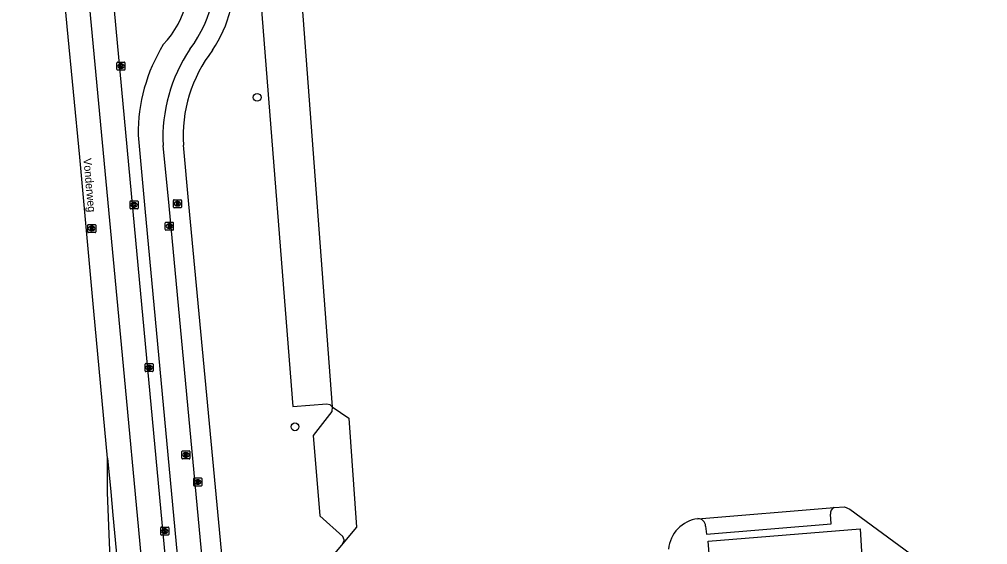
# Model space of a CAD drawing. Extents: x 160676 to 161153, y 383244 to 383713.
# Drawn here: x 160677.6 to 160798.6, y 383378.1 to 383443.8 of the extents above; entities that cross this region are included whole.
import ezdxf

# ---------------------------------------------------------------- set-up
doc = ezdxf.new("R2010")
doc.units = 0
for name, color, linetype in [('IMGEO_Boom', 7, 'Continuous'), ('IMGEO_Fietspad_gesloten', 7, 'Continuous'), ('IMGEO_Groenvoorziening', 7, 'Continuous'), ('IMGEO_Hek', 7, 'Continuous'), ('IMGEO_Kolk', 7, 'Continuous'), ('IMGEO_Openbare_ruimte_label', 7, 'Continuous'), ('IMGEO_Parkeervlak_open', 7, 'Continuous'), ('IMGEO_Rijbaan_lokaal_gesloten', 7, 'Continuous'), ('IMGEO_Rioolput', 7, 'Continuous')]:
    doc.layers.add(name, color=color, linetype=linetype)

msp = doc.modelspace()

# ---------------------------------------------------------------- linework, layer by layer
at = {"layer": 'IMGEO_Boom'}
for centre in [(160707.3, 383434.03), (160712.03, 383392.85)]:
    msp.add_circle(centre, 0.489, dxfattribs=at)
at = {"layer": 'IMGEO_Fietspad_gesloten'}
msp.add_lwpolyline([(160692.44, 383429.3), (160693.25, 383420.12), (160702.06, 383325.99)], dxfattribs=at)
for centre, radius, start, end in [((160686.43, 383449.15), 12.5, 316.976, 14.7951), ((160713.6, 383429.54), 21.16, 148.4252, 180.641)]:
    msp.add_arc(centre, radius, start, end, dxfattribs=at)
at = {"layer": 'IMGEO_Groenvoorziening'}
for points in [[(160716.66, 383395.36), (160716.62, 383394.75), (160714.28, 383391.75), (160715.13, 383381.71), (160717.99, 383379.14)], [(160716.66, 383395.36), (160718.76, 383393.94), (160719.72, 383380.29), (160718.01, 383378.28)], [(160779.4, 383382.76), (160780.68, 383382.83), (160781.33, 383382.57), (160797.05, 383371.03), (160798.57, 383369.85)], [(160718.01, 383378.28), (160715.22, 383374.89), (160718.08, 383337.73), (160724.09, 383332.46)]]:
    msp.add_lwpolyline(points, dxfattribs=at)
for centre, radius, start, end in [((160762.93, 383377.14), 4.26, 97.7114, 174.5244), ((160717.46, 383378.69), 0.693, 323.4414, 39.9004)]:
    msp.add_arc(centre, radius, start, end, dxfattribs=at)
at = {"layer": 'IMGEO_Hek'}
msp.add_lwpolyline([(160714.62, 383330.06), (160733.58, 383331.54), (160748.09, 383332.67), (160751.06, 383333.55), (160755.17, 383335.39), (160766.7, 383340.55), (160766.49, 383343.2), (160763.64, 383378.57), (160782.62, 383380.08), (160783.16, 383371.62), (160791.42, 383362.83), (160798.57, 383369.85)], dxfattribs=at)
at = {"layer": 'IMGEO_Kolk'}
for p, q in [((160689.79, 383437.51), (160689.79, 383438.36)), ((160689.86, 383438.43), (160690.72, 383438.43)), ((160690.28, 383438.21), (160690.3, 383438.21)), ((160690.79, 383438.36), (160690.79, 383437.51)), ((160690.72, 383437.43), (160689.86, 383437.43)), ((160690.3, 383437.65), (160690.28, 383437.65)), ((160691.42, 383420.17), (160691.42, 383421.02)), ((160691.49, 383421.1), (160692.35, 383421.1)), ((160691.91, 383420.87), (160691.93, 383420.87)), ((160692.42, 383421.02), (160692.42, 383420.17)), ((160692.35, 383420.09), (160691.49, 383420.09)), ((160691.93, 383420.32), (160691.91, 383420.32)), ((160693.31, 383399.83), (160693.31, 383400.68)), ((160693.38, 383400.75), (160694.23, 383400.75)), ((160693.79, 383400.53), (160693.82, 383400.53)), ((160694.31, 383400.68), (160694.31, 383399.83)), ((160694.23, 383399.75), (160693.38, 383399.75)), ((160693.82, 383399.97), (160693.79, 383399.97)), ((160695.26, 383379.38), (160695.26, 383380.24)), ((160695.33, 383380.31), (160696.19, 383380.31)), ((160695.75, 383380.09), (160695.77, 383380.09)), ((160696.26, 383380.24), (160696.26, 383379.38)), ((160696.19, 383379.31), (160695.33, 383379.31)), ((160695.77, 383379.53), (160695.75, 383379.53))]:
    msp.add_line(p, q, dxfattribs=at)
for points in [[(160689.79, 383437.51), (160689.79, 383438.36)], [(160689.86, 383438.43), (160690.72, 383438.43)], [(160690.11, 383438.13), (160690.23, 383438.13), (160690.23, 383437.98), (160690.36, 383438.13), (160690.53, 383438.13), (160690.38, 383437.98), (160690.53, 383437.73), (160690.38, 383437.73), (160690.3, 383437.9), (160690.23, 383437.83), (160690.23, 383437.73), (160690.11, 383437.73), (160690.11, 383438.13)], [(160690.79, 383438.36), (160690.79, 383437.51)], [(160690.72, 383437.43), (160689.86, 383437.43)], [(160691.42, 383420.17), (160691.42, 383421.02)], [(160691.49, 383421.1), (160692.35, 383421.1)], [(160691.74, 383420.79), (160691.86, 383420.79), (160691.86, 383420.64), (160691.99, 383420.79), (160692.16, 383420.79), (160692.01, 383420.64), (160692.16, 383420.39), (160692.01, 383420.39), (160691.93, 383420.56), (160691.86, 383420.49), (160691.86, 383420.39), (160691.74, 383420.39), (160691.74, 383420.79)], [(160692.42, 383421.02), (160692.42, 383420.17)], [(160692.35, 383420.09), (160691.49, 383420.09)], [(160693.31, 383399.83), (160693.31, 383400.68)], [(160693.38, 383400.75), (160694.23, 383400.75)], [(160693.63, 383400.45), (160693.75, 383400.45), (160693.75, 383400.3), (160693.88, 383400.45), (160694.04, 383400.45), (160693.9, 383400.3), (160694.05, 383400.05), (160693.9, 383400.05), (160693.81, 383400.22), (160693.75, 383400.15), (160693.75, 383400.05), (160693.63, 383400.05), (160693.63, 383400.45)], [(160694.31, 383400.68), (160694.31, 383399.83)], [(160694.23, 383399.75), (160693.38, 383399.75)], [(160695.26, 383379.38), (160695.26, 383380.24)], [(160695.33, 383380.31), (160696.19, 383380.31)], [(160695.58, 383380.01), (160695.7, 383380.01), (160695.7, 383379.86), (160695.83, 383380.01), (160696, 383380.01), (160695.85, 383379.86), (160696, 383379.61), (160695.85, 383379.61), (160695.77, 383379.77), (160695.7, 383379.71), (160695.7, 383379.61), (160695.58, 383379.61), (160695.58, 383380.01)], [(160696.26, 383380.24), (160696.26, 383379.38)], [(160696.19, 383379.31), (160695.33, 383379.31)]]:
    msp.add_lwpolyline(points, dxfattribs=at)
for centre, start, end in [((160689.87, 383438.36), 91.552, 178.448), ((160689.87, 383438.36), 91.552, 178.448), ((160690.71, 383438.36), 1.552, 88.448), ((160690.71, 383438.36), 1.552, 88.448), ((160689.87, 383437.51), 181.552, 268.448), ((160689.87, 383437.51), 181.552, 268.448), ((160690.71, 383437.51), 271.552, 358.448), ((160690.71, 383437.51), 271.552, 358.448), ((160691.5, 383421.02), 91.552, 178.448), ((160691.5, 383421.02), 91.552, 178.448), ((160692.34, 383421.02), 1.552, 88.448), ((160692.34, 383421.02), 1.552, 88.448), ((160691.5, 383420.17), 181.552, 268.448), ((160691.5, 383420.17), 181.552, 268.448), ((160692.34, 383420.17), 271.552, 358.448), ((160692.34, 383420.17), 271.552, 358.448), ((160693.38, 383400.68), 91.552, 178.448), ((160693.38, 383400.68), 91.552, 178.448), ((160694.23, 383400.68), 1.552, 88.448), ((160694.23, 383400.68), 1.552, 88.448), ((160693.38, 383399.83), 181.552, 268.448), ((160693.38, 383399.83), 181.552, 268.448), ((160694.23, 383399.83), 271.552, 358.448), ((160694.23, 383399.83), 271.552, 358.448), ((160695.34, 383380.23), 91.552, 178.448), ((160695.34, 383380.23), 91.552, 178.448), ((160696.18, 383380.23), 1.552, 88.448), ((160696.18, 383380.23), 1.552, 88.448), ((160695.34, 383379.38), 181.552, 268.448), ((160695.34, 383379.38), 181.552, 268.448), ((160696.18, 383379.38), 271.552, 358.448), ((160696.18, 383379.38), 271.552, 358.448)]:
    msp.add_arc(centre, 0.0765, start, end, dxfattribs=at)
for centre, major_axis, ratio, start_param, end_param in [((160690.28, 383437.93), (-0.387, 0.002), 0.722429, 4.712389, 7.853982), ((160690.3, 383437.93), (-0.39, 0.002), 0.717154, 1.570796, 4.712389), ((160691.91, 383420.59), (-0.387, 0.002), 0.722429, 4.712389, 7.853982), ((160691.93, 383420.59), (-0.39, 0.002), 0.717154, 1.570796, 4.712389), ((160693.79, 383400.25), (-0.387, 0.002), 0.722429, 4.712389, 7.853982), ((160693.82, 383400.25), (-0.39, 0.002), 0.717154, 1.570796, 4.712389), ((160695.75, 383379.81), (-0.387, 0.002), 0.722429, 4.712389, 7.853982), ((160695.77, 383379.81), (-0.39, 0.002), 0.717154, 1.570796, 4.712389)]:
    msp.add_ellipse(centre, major_axis=major_axis, ratio=ratio, start_param=start_param, end_param=end_param, dxfattribs=at)
at = {"layer": 'IMGEO_Parkeervlak_open'}
for points in [[(160712.87, 383445.9), (160707.8, 383445.49), (160711.74, 383395.38), (160716.01, 383395.73), (160716.39, 383395.65), (160716.66, 383395.36)], [(160712.87, 383445.9), (160716.66, 383395.36)], [(160762.36, 383381.36), (160779.4, 383382.76)], [(160763.31, 383380.43), (160763.44, 383379.43), (160779.02, 383380.73), (160778.95, 383381.92)]]:
    msp.add_lwpolyline(points, dxfattribs=at)
for centre, radius, start, end in [((160779.72, 383382.05), 0.782, 114.0525, 189.2157), ((160762.42, 383380.48), 0.891, 357.1695, 93.5628)]:
    msp.add_arc(centre, radius, start, end, dxfattribs=at)
at = {"layer": 'IMGEO_Rijbaan_lokaal_gesloten'}
for points in [[(160688.61, 383388.91), (160686.9, 383407.32), (160685.13, 383426.54), (160683.55, 383442.89), (160682.06, 383459), (160680.73, 383472.86), (160679.27, 383486.72), (160678.36, 383494.52), (160677.59, 383502.31)], [(160699.23, 383308.29), (160696.66, 383336.41), (160692.9, 383375.91), (160692.5, 383379.97), (160690.74, 383399.13), (160687.97, 383428.37), (160683.4, 383477.16)], [(160702.42, 383307.77), (160702.35, 383308.39), (160700.52, 383326.38), (160692.14, 383416.19), (160688.6, 383454.35), (160688.45, 383455.82)], [(160705.03, 383327.48), (160696.31, 383420.48), (160695.54, 383428.02)], [(160707.33, 383329.61), (160698.78, 383420.67), (160698.1, 383428.04)], [(160691.54, 383309.35), (160691.49, 383311.74), (160691.1, 383321.26), (160690.84, 383327.37), (160689.89, 383351.36), (160689.11, 383372.17), (160688.6, 383384.62), (160688.61, 383388.91)], [(160688.61, 383388.91), (160689.02, 383384.71), (160689.29, 383381.8), (160691.24, 383361.07), (160692.21, 383350.41), (160693.01, 383340.3), (160694.06, 383326.73), (160694.98, 383313.28)]]:
    msp.add_lwpolyline(points, dxfattribs=at)
for centre, radius, start, end in [((160686.31, 383449.54), 15.77, 323.008, 14.2898), ((160688.21, 383448.93), 16.25, 326.3214, 5.1534), ((160715.34, 383428.97), 19.82, 146.0089, 182.7529), ((160715.54, 383429.21), 17.48, 142.1962, 183.8175)]:
    msp.add_arc(centre, radius, start, end, dxfattribs=at)
at = {"layer": 'IMGEO_Rioolput'}
for p, q in [((160696.84, 383420.3), (160696.84, 383421.15)), ((160696.91, 383421.23), (160697.77, 383421.23)), ((160697.33, 383421.01), (160697.35, 383421.01)), ((160697.84, 383421.15), (160697.84, 383420.3)), ((160697.77, 383420.23), (160696.91, 383420.23)), ((160697.35, 383420.45), (160697.32, 383420.45)), ((160695.83, 383417.5), (160695.83, 383418.36)), ((160695.91, 383418.43), (160696.76, 383418.43)), ((160696.83, 383418.36), (160696.83, 383417.5)), ((160686.14, 383417.21), (160686.14, 383418.06)), ((160686.21, 383418.14), (160687.06, 383418.14)), ((160687.06, 383417.14), (160686.21, 383417.14)), ((160686.62, 383417.92), (160686.65, 383417.92)), ((160686.65, 383417.36), (160686.62, 383417.36)), ((160687.14, 383418.06), (160687.14, 383417.21)), ((160696.76, 383417.43), (160695.91, 383417.43)), ((160696.32, 383418.21), (160696.35, 383418.21)), ((160696.34, 383417.65), (160696.32, 383417.65)), ((160697.9, 383388.92), (160697.9, 383389.77)), ((160697.97, 383389.84), (160698.83, 383389.84)), ((160698.39, 383389.62), (160698.41, 383389.62)), ((160698.9, 383389.77), (160698.9, 383388.92)), ((160698.83, 383388.84), (160697.97, 383388.84)), ((160698.41, 383389.06), (160698.38, 383389.06)), ((160699.39, 383385.52), (160699.39, 383386.38)), ((160699.46, 383386.45), (160700.32, 383386.45)), ((160699.88, 383386.23), (160699.9, 383386.23)), ((160700.39, 383386.38), (160700.39, 383385.52)), ((160700.32, 383385.45), (160699.46, 383385.45)), ((160699.9, 383385.67), (160699.87, 383385.67))]:
    msp.add_line(p, q, dxfattribs=at)
for points in [[(160696.84, 383420.3), (160696.84, 383421.15)], [(160696.91, 383421.23), (160697.77, 383421.23)], [(160697.43, 383420.92), (160697.18, 383420.93), (160697.18, 383420.53)], [(160697.35, 383420.85), (160697.3, 383420.85), (160697.3, 383420.76)], [(160697.3, 383420.76), (160697.35, 383420.76)], [(160697.84, 383421.15), (160697.84, 383420.3)], [(160697.77, 383420.23), (160696.91, 383420.23)], [(160697.18, 383420.53), (160697.3, 383420.53), (160697.3, 383420.69), (160697.31, 383420.69)], [(160697.36, 383420.66), (160697.43, 383420.53), (160697.57, 383420.53), (160697.5, 383420.65)], [(160695.83, 383417.5), (160695.83, 383418.36)], [(160695.91, 383418.43), (160696.76, 383418.43)], [(160696.83, 383418.36), (160696.83, 383417.5)], [(160686.14, 383417.21), (160686.14, 383418.06)], [(160686.21, 383418.14), (160687.06, 383418.14)], [(160687.06, 383417.14), (160686.21, 383417.14)], [(160686.73, 383417.83), (160686.47, 383417.84), (160686.47, 383417.44)], [(160686.47, 383417.44), (160686.6, 383417.44), (160686.6, 383417.6), (160686.61, 383417.6)], [(160686.65, 383417.76), (160686.6, 383417.76), (160686.6, 383417.67)], [(160686.6, 383417.67), (160686.65, 383417.67)], [(160686.65, 383417.57), (160686.73, 383417.44), (160686.87, 383417.44), (160686.8, 383417.56)], [(160687.14, 383418.06), (160687.14, 383417.21)], [(160696.76, 383417.43), (160695.91, 383417.43)], [(160696.42, 383418.13), (160696.17, 383418.13), (160696.17, 383417.73)], [(160696.17, 383417.73), (160696.29, 383417.73), (160696.29, 383417.89), (160696.3, 383417.89)], [(160696.35, 383418.05), (160696.29, 383418.05), (160696.29, 383417.97)], [(160696.29, 383417.97), (160696.34, 383417.97)], [(160696.35, 383417.86), (160696.42, 383417.73), (160696.56, 383417.73), (160696.5, 383417.86)], [(160697.9, 383388.92), (160697.9, 383389.77)], [(160697.97, 383389.84), (160698.83, 383389.84)], [(160698.49, 383389.54), (160698.23, 383389.54), (160698.23, 383389.14)], [(160698.23, 383389.14), (160698.36, 383389.14), (160698.36, 383389.31), (160698.37, 383389.31)], [(160698.41, 383389.46), (160698.36, 383389.46), (160698.36, 383389.38)], [(160698.36, 383389.38), (160698.41, 383389.38)], [(160698.9, 383389.77), (160698.9, 383388.92)], [(160698.83, 383388.84), (160697.97, 383388.84)], [(160698.42, 383389.28), (160698.49, 383389.14), (160698.63, 383389.14), (160698.56, 383389.27)], [(160699.39, 383385.52), (160699.39, 383386.38)], [(160699.46, 383386.45), (160700.32, 383386.45)], [(160699.98, 383386.15), (160699.72, 383386.15), (160699.72, 383385.75)], [(160699.72, 383385.75), (160699.85, 383385.75), (160699.85, 383385.91), (160699.86, 383385.91)], [(160699.9, 383386.07), (160699.85, 383386.07), (160699.85, 383385.99)], [(160699.85, 383385.99), (160699.9, 383385.99)], [(160699.91, 383385.88), (160699.98, 383385.75), (160700.12, 383385.75), (160700.05, 383385.88)], [(160700.39, 383386.38), (160700.39, 383385.52)], [(160700.32, 383385.45), (160699.46, 383385.45)]]:
    msp.add_lwpolyline(points, dxfattribs=at)
for centre, radius, start, end in [((160696.92, 383421.15), 0.0765, 91.552, 178.448), ((160696.92, 383421.15), 0.0765, 91.552, 178.448), ((160697.36, 383420.75), 0.0964, 77.0061, 93.1865), ((160697.34, 383420.95), 0.19, 274.7715, 282.9687), ((160697.37, 383420.81), 0.0378, 276.6634, 79.6772), ((160697.43, 383420.81), 0.109, 350.3612, 89.416), ((160697.43, 383420.81), 0.112, 277.5842, 350.9817), ((160697.76, 383421.15), 0.0765, 1.552, 88.448), ((160697.76, 383421.15), 0.0765, 1.552, 88.448), ((160696.92, 383420.3), 0.0765, 181.552, 268.448), ((160696.92, 383420.3), 0.0765, 181.552, 268.448), ((160697.31, 383420.64), 0.0533, 26.0293, 88.6989), ((160697.41, 383420.6), 0.108, 29.5134, 73.7905), ((160697.76, 383420.3), 0.0765, 271.552, 358.448), ((160697.76, 383420.3), 0.0765, 271.552, 358.448), ((160695.91, 383418.35), 0.0765, 91.552, 178.448), ((160695.91, 383418.35), 0.0765, 91.552, 178.448), ((160696.76, 383418.35), 0.0765, 1.552, 88.448), ((160696.76, 383418.35), 0.0765, 1.552, 88.448), ((160686.21, 383418.06), 0.0765, 91.552, 178.448), ((160686.21, 383418.06), 0.0765, 91.552, 178.448), ((160686.21, 383417.21), 0.0765, 181.552, 268.448), ((160686.21, 383417.21), 0.0765, 181.552, 268.448), ((160686.61, 383417.55), 0.0533, 26.0293, 88.6989), ((160686.66, 383417.66), 0.0964, 77.0061, 93.1865), ((160686.63, 383417.86), 0.19, 274.7715, 282.9687), ((160686.67, 383417.72), 0.0378, 276.6634, 79.6772), ((160686.72, 383417.72), 0.109, 350.3612, 89.416), ((160686.72, 383417.72), 0.112, 277.5842, 350.9817), ((160686.71, 383417.51), 0.108, 29.5134, 73.7905), ((160687.06, 383418.06), 0.0765, 1.552, 88.448), ((160687.06, 383418.06), 0.0765, 1.552, 88.448), ((160687.06, 383417.21), 0.0765, 271.552, 358.448), ((160687.06, 383417.21), 0.0765, 271.552, 358.448), ((160695.91, 383417.5), 0.0765, 181.552, 268.448), ((160695.91, 383417.5), 0.0765, 181.552, 268.448), ((160696.3, 383417.84), 0.0533, 26.0293, 88.6989), ((160696.33, 383418.16), 0.19, 274.7715, 282.9687), ((160696.35, 383417.95), 0.0964, 77.0061, 93.1865), ((160696.37, 383418.01), 0.0378, 276.6634, 79.6772), ((160696.42, 383418.02), 0.109, 350.3612, 89.416), ((160696.42, 383418.02), 0.112, 277.5842, 350.9817), ((160696.4, 383417.8), 0.108, 29.5134, 73.7905), ((160696.76, 383417.5), 0.0765, 271.552, 358.448), ((160696.76, 383417.5), 0.0765, 271.552, 358.448), ((160697.97, 383389.77), 0.0765, 91.552, 178.448), ((160697.97, 383389.77), 0.0765, 91.552, 178.448), ((160698.37, 383389.25), 0.0533, 26.0293, 88.6989), ((160698.42, 383389.37), 0.0964, 77.0061, 93.1865), ((160698.4, 383389.57), 0.19, 274.7715, 282.9687), ((160698.43, 383389.42), 0.0378, 276.6634, 79.6772), ((160698.49, 383389.43), 0.109, 350.3612, 89.416), ((160698.48, 383389.43), 0.112, 277.5842, 350.9817), ((160698.47, 383389.22), 0.108, 29.5134, 73.7905), ((160698.82, 383389.77), 0.0765, 1.552, 88.448), ((160698.82, 383389.77), 0.0765, 1.552, 88.448), ((160697.97, 383388.92), 0.0765, 181.552, 268.448), ((160697.97, 383388.92), 0.0765, 181.552, 268.448), ((160698.82, 383388.92), 0.0765, 271.552, 358.448), ((160698.82, 383388.92), 0.0765, 271.552, 358.448), ((160699.46, 383386.38), 0.0765, 91.552, 178.448), ((160699.46, 383386.38), 0.0765, 91.552, 178.448), ((160699.86, 383385.86), 0.0533, 26.0293, 88.6989), ((160699.91, 383385.97), 0.0964, 77.0061, 93.1865), ((160699.89, 383386.18), 0.19, 274.7715, 282.9687), ((160699.92, 383386.03), 0.0378, 276.6634, 79.6772), ((160699.98, 383386.04), 0.109, 350.3612, 89.416), ((160699.97, 383386.04), 0.112, 277.5842, 350.9817), ((160699.96, 383385.82), 0.108, 29.5134, 73.7905), ((160700.31, 383386.38), 0.0765, 1.552, 88.448), ((160700.31, 383386.38), 0.0765, 1.552, 88.448), ((160699.46, 383385.53), 0.0765, 181.552, 268.448), ((160699.46, 383385.53), 0.0765, 181.552, 268.448), ((160700.31, 383385.53), 0.0765, 271.552, 358.448), ((160700.31, 383385.53), 0.0765, 271.552, 358.448)]:
    msp.add_arc(centre, radius, start, end, dxfattribs=at)
for centre, major_axis, ratio, start_param, end_param in [((160697.33, 383420.73), (-0.387, 0.002), 0.722429, 4.712389, 7.853982), ((160697.35, 383420.73), (-0.39, 0.002), 0.717154, 1.570796, 4.712389), ((160686.62, 383417.64), (-0.387, 0.002), 0.722429, 4.712389, 7.853982), ((160686.65, 383417.64), (-0.39, 0.002), 0.717154, 1.570796, 4.712389), ((160696.32, 383417.93), (-0.387, 0.002), 0.722429, 4.712389, 7.853982), ((160696.34, 383417.93), (-0.39, 0.002), 0.717154, 1.570796, 4.712389), ((160698.39, 383389.34), (-0.387, 0.002), 0.722429, 4.712389, 7.853982), ((160698.41, 383389.34), (-0.39, 0.002), 0.717154, 1.570796, 4.712389), ((160699.88, 383385.95), (-0.387, 0.002), 0.722429, 4.712389, 7.853982), ((160699.9, 383385.95), (-0.39, 0.002), 0.717154, 1.570796, 4.712389)]:
    msp.add_ellipse(centre, major_axis=major_axis, ratio=ratio, start_param=start_param, end_param=end_param, dxfattribs=at)

# ---------------------------------------------------------------- texts
at = {"layer": 'IMGEO_Openbare_ruimte_label'}
msp.add_text('Vonderweg', height=1, rotation=274.9921, dxfattribs=at).set_placement((160685.59, 383426.38))

doc.saveas('drawing.dxf')
